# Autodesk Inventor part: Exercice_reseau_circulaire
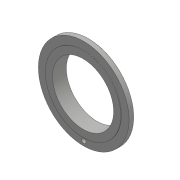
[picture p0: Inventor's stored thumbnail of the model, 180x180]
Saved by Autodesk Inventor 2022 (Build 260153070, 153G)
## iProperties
Created: 2018-03
Part Number: Exercice_reseau_circulaire
Material: Fonte, ductile
Document SubType Name: Modeling
Designer: booth09-mgr2
Density: 7.15 g/cm^3
Appearance: Gris clair
Stock Number: bri-Fonte-300
Mass: 18674.6 g
Surface Area: 3121.94 cm^2
Volume: 2611.83 cm^3
g1: 370,000 mm
D: 445,000 mm
Author: booth09-mgr2
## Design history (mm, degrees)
sketch "Esquisse1"
  geometry: L1 (0, 0)-(0, 68); L2 (-222.5, 3)-(-222.5, 26); L3 (-222.5, 26)-(-172.5, 26); L4 (-172.5, 26)-(-161.5, 58); L5 (-161.5, 58)-(-161.5, 68); L6 (-161.5, 68)-(-150, 68); L7 (-222.5, 3)-(-185, 3); L8 (-185, 3)-(-185, 0); L9 (-185, 0)-(-150, 0); L10 (-150, 0)-(-150, 68)
  constraints: 21 end point, 4 perpendicular, 2 horizontal alignment, 2 vertical, 1 horizontal, 1 parallel
  dimensions: "g1" = 370 diameter of L8 L1; "D" = 445 diameter of L2 L1; "d" = 323 diameter of L5 L1; "d4" = 3 distance of L7.end L8.end; "d5" = 10 distance of L4.end L5.end; "h1" = 68 distance of L1.start L1.end; "d7" = 50 distance of L2.end L3.end; "DN" = 300 diameter of L10 L1; "b" = 26 distance between parallel lines of L9 L3
revolve "Révolution1" sketch "Esquisse1" stored, may be unused: angle "d9" = 90 deg
fillet "Congé1" dims "d10" = 2
node "Plan de construction1"
sketch "Esquisse2"
  geometry: L1 (0, 0)-(150, 0); 2 further points
  constraints: 2 end point, 1 horizontal, 1 symmetric about line, 1 vertical alignment
  dimensions: "C1" = 400 distance of point (0, -200) point (0, 200)
hole "Perçage1" sketch "Esquisse2" diameter "O" = 22; stored, may be unused: countersink angle "d21" = 90 deg, drill point angle "d23" = 118 deg; dims "d18" = 6, "d19" = 4, "d20" = 2, "d22" = 8
node "Solide1"
